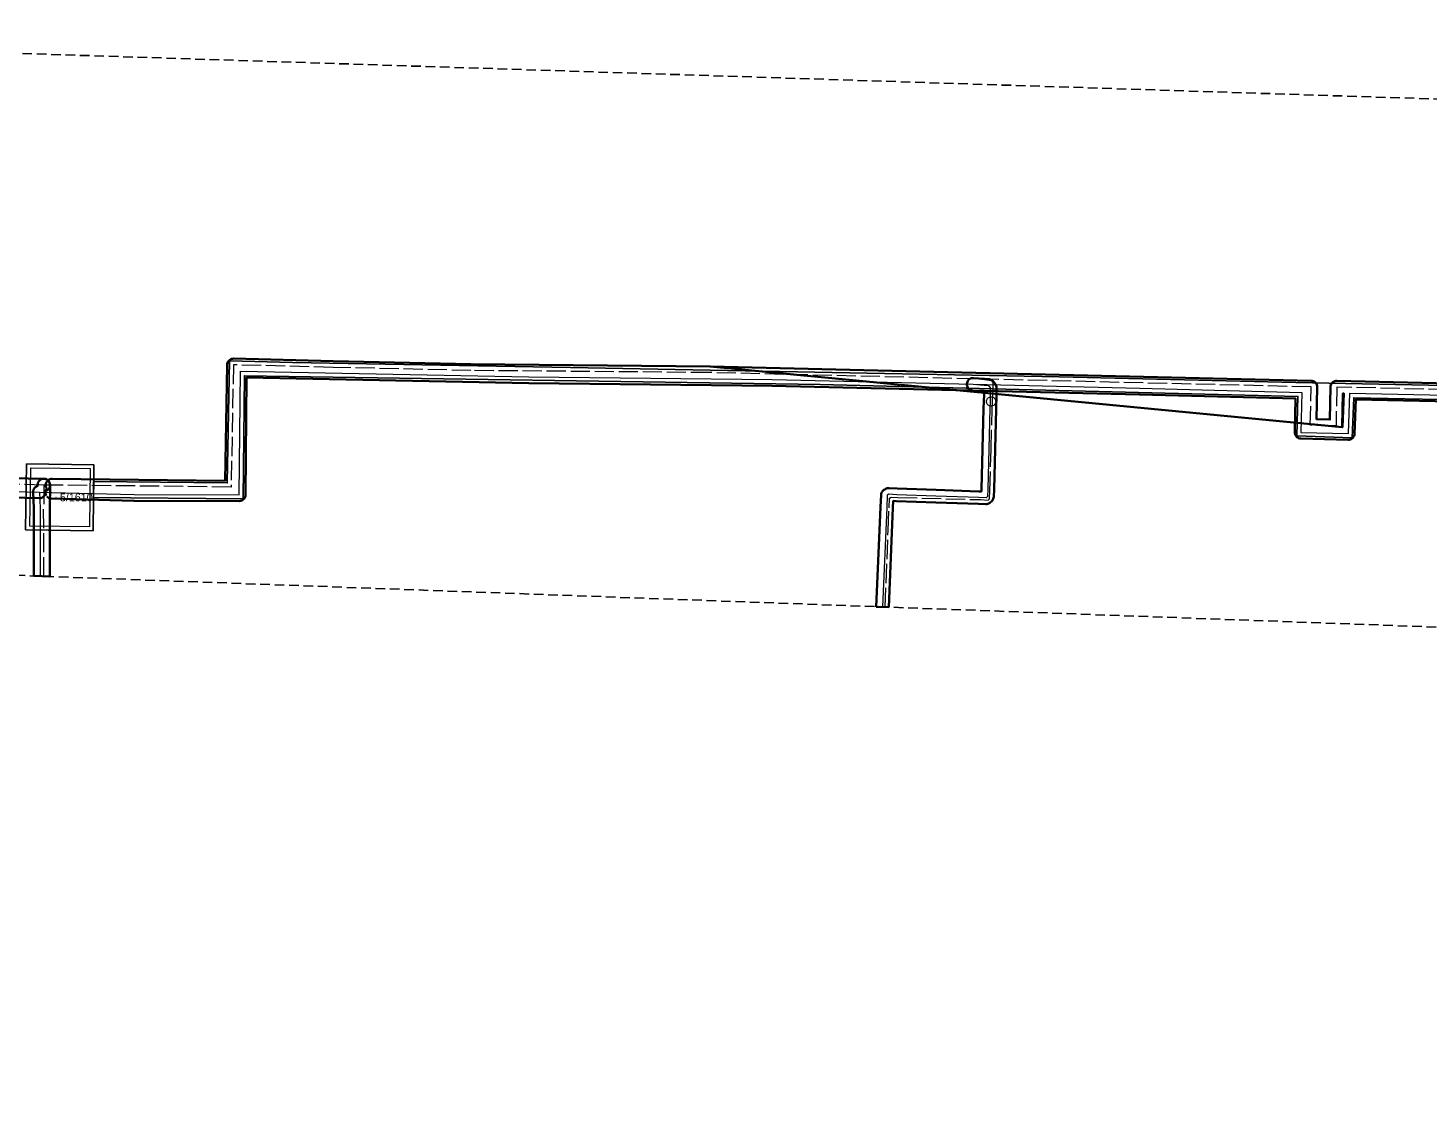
# Model space of a CAD drawing. Extents: x -451331 to -449998, y -1101254 to -1101132.
# Drawn here: x -451240.9 to -451083.4, y -1101253.5 to -1101132.1 of the extents above; entities that cross this region are included whole.
import ezdxf

# ---------------------------------------------------------------- set-up
doc = ezdxf.new("R2010")
doc.units = 0
doc.header["$LTSCALE"] = 0.36
doc.linetypes.add('LONG_DASHED', pattern=[7.5, 6, -1.5])
doc.linetypes.add('MEDIUM_DASHED', pattern=[4.5, 3, -1.5])
for name, color, linetype, lineweight in [('2', 7, 'Continuous', 13), ('3', 7, 'Continuous', 25), ('62', 7, 'MEDIUM_DASHED', 25), ('8', 7, 'Continuous', 35)]:
    doc.layers.add(name, color=color, linetype=linetype, lineweight=lineweight)

msp = doc.modelspace()

# ---------------------------------------------------------------- linework, layer by layer
at = {"layer": '2'}
for p, q in [((-451239.584, -1101184.268), (-451238.191, -1101184.303)), ((-451239.584, -1101184.268), (-451239.5, -1101186.067)), ((-451239.5, -1101186.067), (-451239.491, -1101193.726))]:
    msp.add_line(p, q, dxfattribs=at)
at = {"layer": '2', "linetype": 'LONG_DASHED'}
for p, q in [((-451239.081, -1101183.474), (-451239.1, -1101186.056)), ((-451238.164, -1101183.484), (-451239.081, -1101183.474)), ((-451237.714, -1101184.841), (-451237.691, -1101184.842)), ((-451239.091, -1101193.74), (-451239.1, -1101186.056))]:
    msp.add_line(p, q, dxfattribs=at)
at = {"layer": '2'}
for points in [[(-451262.272, -1101134.293), (-451261.769, -1101137.772), (-451249.372, -1101141.048), (-451249.333, -1101184.03), (-451239.584, -1101184.268)], [(-451238.191, -1101184.303), (-451228.935, -1101184.54), (-451217.098, -1101184.579), (-451216.979, -1101170.692), (-451184.527, -1101171.317), (-451157.179, -1101171.61), (-451134.59, -1101172.149)], [(-451134.59, -1101172.149), (-451115.837, -1101172.598), (-451097.604, -1101173.075), (-451097.719, -1101177.554), (-451092.388, -1101177.693), (-451092.213, -1101173.145), (-451061.616, -1101173.805)], [(-451134.59, -1101172.149), (-451133.347, -1101172.242), (-451132.849, -1101172.279), (-451132.649, -1101172.539), (-451132.659, -1101173.309), (-451132.68, -1101174.106)], [(-451132.68, -1101174.106), (-451132.7, -1101174.879), (-451132.929, -1101183.96), (-451132.97, -1101184.78), (-451133.13, -1101184.93), (-451133.95, -1101184.89), (-451138.763, -1101184.728), (-451143.159, -1101184.579), (-451144.079, -1101184.519), (-451144.24, -1101184.62), (-451144.299, -1101186), (-451144.777, -1101197.179)]]:
    msp.add_lwpolyline(points, dxfattribs=at)
at = {"layer": '2', "linetype": 'LONG_DASHED'}
for points in [[(-451239.081, -1101183.474), (-451248.694, -1101183.268), (-451248.77, -1101170.376), (-451247.913, -1101169.853), (-451248.046, -1101147.205), (-451248.909, -1101146.643), (-451248.945, -1101140.461), (-451261.395, -1101137.3), (-451261.842, -1101134.307)], [(-451134.264, -1101171.549), (-451164.178, -1101170.835), (-451191.059, -1101170.599), (-451206.561, -1101170.249), (-451217.766, -1101169.965), (-451218.01, -1101183.701), (-451238.164, -1101183.484)], [(-451061.444, -1101173.121), (-451065.019, -1101173.141), (-451093.694, -1101172.465), (-451093.775, -1101176.839), (-451096.67, -1101176.755), (-451096.583, -1101172.448), (-451134.264, -1101171.549)], [(-451132.403, -1101174.097), (-451132.369, -1101173.379), (-451132.34, -1101172.73), (-451132.329, -1101171.94), (-451132.49, -1101171.78), (-451133.587, -1101171.628), (-451134.264, -1101171.549)], [(-451144.475, -1101197.19), (-451144.135, -1101188.584), (-451144.039, -1101186.039), (-451143.976, -1101184.937), (-451143.817, -1101184.837), (-451143.049, -1101184.87), (-451133.75, -1101185.12), (-451132.89, -1101185.19), (-451132.729, -1101185.039), (-451132.689, -1101184.12), (-451132.563, -1101179.432), (-451132.439, -1101174.879), (-451132.403, -1101174.097)]]:
    msp.add_lwpolyline(points, dxfattribs=at)
at = {"layer": '3'}
for points in [[(-451233.493, -1101184.878), (-451233.467, -1101183.091), (-451218.452, -1101183.247), (-451218.207, -1101169.503), (-451211.129, -1101169.683), (-451179.854, -1101170.248), (-451124.903, -1101171.322), (-451098.285, -1101171.957), (-451062.886, -1101172.679), (-451062.939, -1101174.227), (-451091.782, -1101173.66), (-451091.956, -1101178.155), (-451098.179, -1101177.951), (-451098.066, -1101173.513), (-451151.771, -1101172.189), (-451216.533, -1101171.189), (-451216.652, -1101185.03)], [(-451241.135, -1101188.5), (-451241.025, -1101181.101), (-451233.439, -1101181.214), (-451233.549, -1101188.614)], [(-451240.168, -1101188.515), (-451238.447, -1101188.538), (-451238.441, -1101193.764), (-451240.157, -1101193.702)]]:
    msp.add_lwpolyline(points, close=True, dxfattribs=at)
at = {"layer": '3', "lineweight": 13}
for points in [[(-451132.563, -1101173.571), (-451132.473, -1101173.579), (-451132.386, -1101173.603), (-451132.304, -1101173.641), (-451132.23, -1101173.692), (-451132.167, -1101173.756), (-451132.115, -1101173.83), (-451132.077, -1101173.912), (-451132.054, -1101173.999), (-451132.046, -1101174.088), (-451132.054, -1101174.178), (-451132.077, -1101174.265), (-451132.115, -1101174.347), (-451132.167, -1101174.421), (-451132.23, -1101174.484), (-451132.304, -1101174.536), (-451132.386, -1101174.574), (-451132.473, -1101174.597), (-451132.563, -1101174.605), (-451132.652, -1101174.597), (-451132.74, -1101174.574), (-451132.821, -1101174.536), (-451132.895, -1101174.484), (-451132.959, -1101174.421), (-451133.01, -1101174.347), (-451133.048, -1101174.265), (-451133.072, -1101174.178), (-451133.08, -1101174.088), (-451133.072, -1101173.999), (-451133.048, -1101173.912), (-451133.01, -1101173.83), (-451132.959, -1101173.756), (-451132.895, -1101173.692), (-451132.821, -1101173.641), (-451132.74, -1101173.603), (-451132.652, -1101173.579)], [(-451240.555, -1101181.545), (-451233.887, -1101181.609), (-451233.961, -1101188.17), (-451240.671, -1101188.107)]]:
    msp.add_lwpolyline(points, close=True, dxfattribs=at)
at = {"layer": '62'}
msp.add_lwpolyline([(-450786.261, -1101210.25), (-451322.174, -1101190.711), (-451330.547, -1101132.096), (-450766.722, -1101150.239), (-450459.689, -1101190.711), (-449997.743, -1101194.898), (-449997.743, -1101249.327), (-450456.897, -1101253.514)], close=True, dxfattribs=at)
at = {"layer": '8'}
for points in [[(-451238.796, -1101184.656), (-451238.847, -1101184.549), (-451238.879, -1101184.435), (-451238.891, -1101184.317), (-451238.883, -1101184.199), (-451238.856, -1101184.083), (-451238.809, -1101183.974), (-451238.745, -1101183.875), (-451238.802, -1101183.773), (-451238.841, -1101183.662), (-451238.861, -1101183.547), (-451238.862, -1101183.43), (-451238.843, -1101183.315), (-451238.806, -1101183.204), (-451238.75, -1101183.101), (-451238.678, -1101183.009), (-451238.592, -1101182.93), (-451238.494, -1101182.866), (-451238.386, -1101182.82), (-451238.273, -1101182.792), (-451238.156, -1101182.784), (-451218.697, -1101182.994), (-451218.465, -1101169.952), (-451218.455, -1101169.842), (-451218.427, -1101169.736), (-451218.383, -1101169.634), (-451218.323, -1101169.541), (-451218.25, -1101169.459), (-451218.164, -1101169.389), (-451218.069, -1101169.334), (-451217.966, -1101169.294), (-451217.858, -1101169.271), (-451217.748, -1101169.265), (-451206.544, -1101169.55), (-451191.048, -1101169.899), (-451164.172, -1101170.135), (-451164.161, -1101170.136), (-451093.089, -1101176.975), (-451093.061, -1101176.975), (-451092.915, -1101173.184), (-451093.008, -1101173.182), (-451093.075, -1101176.852), (-451093.079, -1101176.913), (-451093.089, -1101176.975)], [(-451164.161, -1101170.136), (-451096.566, -1101171.748), (-451096.445, -1101171.761), (-451096.328, -1101171.796), (-451096.219, -1101171.85), (-451096.121, -1101171.922), (-451096.037, -1101172.01), (-451095.969, -1101172.111), (-451095.92, -1101172.222), (-451095.891, -1101172.34), (-451095.883, -1101172.462), (-451095.956, -1101176.075), (-451094.462, -1101176.118), (-451094.394, -1101172.452), (-451094.384, -1101172.342), (-451094.356, -1101172.236), (-451094.311, -1101172.135), (-451094.252, -1101172.042), (-451094.179, -1101171.96), (-451094.093, -1101171.89), (-451093.998, -1101171.835), (-451093.895, -1101171.795), (-451093.788, -1101171.772), (-451093.678, -1101171.765), (-451065.013, -1101172.441)], [(-451059.379, -1101174.553), (-451091.54, -1101173.86), (-451091.689, -1101177.72), (-451091.704, -1101177.84), (-451091.74, -1101177.956), (-451091.795, -1101178.064), (-451091.867, -1101178.161), (-451091.956, -1101178.243), (-451092.057, -1101178.31), (-451092.168, -1101178.358), (-451092.286, -1101178.386), (-451092.407, -1101178.393), (-451097.737, -1101178.254), (-451097.859, -1101178.24), (-451097.976, -1101178.205), (-451098.085, -1101178.151), (-451098.183, -1101178.078), (-451098.267, -1101177.99), (-451098.334, -1101177.888), (-451098.383, -1101177.776), (-451098.411, -1101177.657), (-451098.419, -1101177.536), (-451098.322, -1101173.756), (-451115.855, -1101173.297), (-451157.191, -1101172.31), (-451184.534, -1101172.017), (-451184.54, -1101172.017), (-451216.285, -1101171.405), (-451216.398, -1101184.585), (-451216.41, -1101184.706), (-451216.443, -1101184.823), (-451216.495, -1101184.933), (-451216.565, -1101185.032), (-451216.652, -1101185.117), (-451216.752, -1101185.187), (-451216.862, -1101185.238), (-451216.98, -1101185.268), (-451217.101, -1101185.279), (-451228.938, -1101185.24), (-451228.953, -1101185.24), (-451238.209, -1101185.003), (-451238.327, -1101184.99), (-451238.441, -1101184.957), (-451238.548, -1101184.906), (-451238.644, -1101184.837), (-451238.728, -1101184.753)], [(-451247.998, -1101182.583), (-451239.066, -1101182.774), (-451238.95, -1101182.787), (-451238.837, -1101182.818), (-451238.731, -1101182.868), (-451238.635, -1101182.935), (-451238.551, -1101183.017), (-451238.482, -1101183.112), (-451238.43, -1101183.217), (-451238.396, -1101183.329), (-451238.382, -1101183.445), (-451238.387, -1101183.562), (-451238.411, -1101183.677), (-451238.454, -1101183.786), (-451238.515, -1101183.886), (-451238.592, -1101183.975), (-451238.682, -1101184.049), (-451238.784, -1101184.108), (-451238.894, -1101184.149), (-451238.884, -1101184.264), (-451238.893, -1101184.38), (-451238.921, -1101184.493), (-451238.967, -1101184.6), (-451239.031, -1101184.697), (-451239.109, -1101184.783), (-451239.201, -1101184.854), (-451239.303, -1101184.909), (-451239.413, -1101184.947), (-451239.528, -1101184.965), (-451239.601, -1101184.967), (-451249.351, -1101184.729)]]:
    msp.add_lwpolyline(points, dxfattribs=at)
for points in [[(-451145.476, -1101197.153), (-451144.999, -1101185.969), (-451144.939, -1101184.589), (-451144.925, -1101184.477), (-451144.893, -1101184.369), (-451144.844, -1101184.267), (-451144.78, -1101184.174), (-451144.701, -1101184.093), (-451144.611, -1101184.026), (-451144.45, -1101183.926), (-451144.354, -1101183.875), (-451144.25, -1101183.841), (-451144.143, -1101183.822), (-451144.034, -1101183.821), (-451143.125, -1101183.88), (-451138.74, -1101184.028), (-451133.926, -1101184.19), (-451133.915, -1101184.19), (-451133.642, -1101184.204), (-451133.629, -1101183.933), (-451133.399, -1101174.862), (-451133.359, -1101173.296), (-451133.355, -1101172.944), (-451133.399, -1101172.94), (-451134.642, -1101172.848), (-451134.763, -1101172.828), (-451134.878, -1101172.788), (-451134.984, -1101172.728), (-451135.079, -1101172.651), (-451135.159, -1101172.558), (-451135.221, -1101172.453), (-451135.264, -1101172.339), (-451135.287, -1101172.219), (-451135.288, -1101172.097), (-451135.269, -1101171.977), (-451135.229, -1101171.862), (-451135.169, -1101171.755), (-451135.092, -1101171.661), (-451134.999, -1101171.581), (-451134.894, -1101171.519), (-451134.78, -1101171.476), (-451134.66, -1101171.453), (-451134.538, -1101171.451), (-451133.295, -1101171.544), (-451132.795, -1101171.581), (-451132.68, -1101171.6), (-451132.569, -1101171.638), (-451132.466, -1101171.694), (-451132.373, -1101171.766), (-451132.294, -1101171.853), (-451132.094, -1101172.113), (-451132.031, -1101172.211), (-451131.985, -1101172.319), (-451131.958, -1101172.432), (-451131.95, -1101172.549), (-451131.96, -1101173.319), (-451131.96, -1101173.327), (-451132, -1101174.897), (-451132.23, -1101183.977), (-451132.23, -1101183.994), (-451132.271, -1101184.815), (-451132.285, -1101184.921), (-451132.314, -1101185.025), (-451132.36, -1101185.122), (-451132.419, -1101185.212), (-451132.492, -1101185.291), (-451132.652, -1101185.441), (-451132.739, -1101185.511), (-451132.837, -1101185.566), (-451132.943, -1101185.604), (-451133.053, -1101185.626), (-451133.165, -1101185.629), (-451133.979, -1101185.589), (-451138.787, -1101185.427), (-451143.183, -1101185.279), (-451143.205, -1101185.278), (-451143.566, -1101185.254), (-451143.6, -1101186.03), (-451144.077, -1101197.204)], [(-451240.19, -1101193.7), (-451240.2, -1101186.113), (-451240.2, -1101186.099), (-451240.201, -1101186.068), (-451240.283, -1101184.3), (-451240.282, -1101184.222), (-451240.278, -1101184.176), (-451240.27, -1101184.131), (-451240.26, -1101184.087), (-451240.247, -1101184.043), (-451240.231, -1101184), (-451240.212, -1101183.958), (-451240.19, -1101183.918), (-451240.166, -1101183.879), (-451240.139, -1101183.842), (-451240.11, -1101183.806), (-451240.079, -1101183.773), (-451240.045, -1101183.741), (-451240.01, -1101183.712), (-451239.973, -1101183.686), (-451239.934, -1101183.662), (-451239.894, -1101183.64), (-451239.852, -1101183.621), (-451239.809, -1101183.605), (-451239.782, -1101183.597), (-451239.781, -1101183.469), (-451239.771, -1101183.354), (-451239.742, -1101183.242), (-451239.695, -1101183.136), (-451239.631, -1101183.04), (-451239.553, -1101182.955), (-451239.461, -1101182.885), (-451239.359, -1101182.83), (-451239.249, -1101182.793), (-451239.135, -1101182.775), (-451239.02, -1101182.775), (-451238.906, -1101182.795), (-451238.796, -1101182.833), (-451238.695, -1101182.889), (-451238.604, -1101182.96), (-451238.527, -1101183.046), (-451238.464, -1101183.143), (-451238.418, -1101183.249), (-451238.39, -1101183.361), (-451238.381, -1101183.477), (-451238.4, -1101186.055), (-451238.4, -1101186.061), (-451238.391, -1101193.766)]]:
    msp.add_lwpolyline(points, close=True, dxfattribs=at)

# ---------------------------------------------------------------- texts
at = {"layer": '3'}
msp.add_text('5/1610 ', height=0.9, dxfattribs=at).set_placement((-451237.269, -1101185.31))

doc.saveas('drawing.dxf')
